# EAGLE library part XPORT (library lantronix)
Serial to 10/100 Ethernet transceiver Source: http://www.lantronix.com/pdf/XPort_DS.pdf
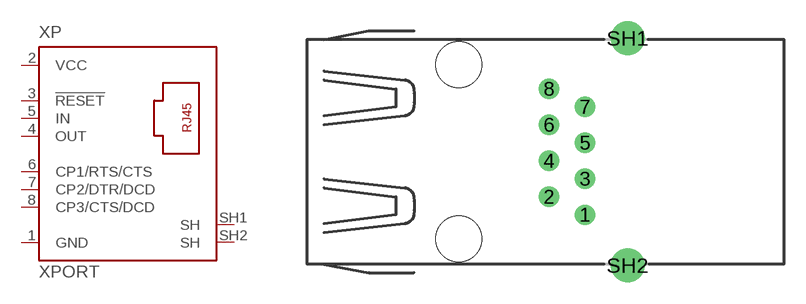
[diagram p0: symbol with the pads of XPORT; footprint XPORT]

Designator prefix XP

## XPORT (OC_FARNELL: unknown; OC_NEWARK: unknown)  [XPORT]
1  GND  pwr
2  VCC  pwr
3  !RESET  in
4  OUT  out
5  IN  in
6  CP1/RTS/CTS
7  CP2/DTR/DCD
8  CP3/CTS/DCD
SH1  SH  pas
SH2  SH  pas

## Footprint XPORT (pad centres in mm)
Serial to 10/100 Ethernet transceiver Source: http://www.lantronix.com/pdf/XPort_DS.pdf
drill 0.9 pad 1.422 round: 1 1.27,-4.445; 2 -1.27,-3.175; 3 1.27,-1.905; 4 -1.27,-0.635; 5 1.27,0.635; 6 -1.27,1.905; 7 1.27,3.175; 8 -1.27,4.445
drill 1.6 pad 2.2 round: SH1 4.28,8.025; SH2 4.28,-8.025
hole 3.25 at -7.62,-6.15
hole 3.25 at -7.62,6.15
